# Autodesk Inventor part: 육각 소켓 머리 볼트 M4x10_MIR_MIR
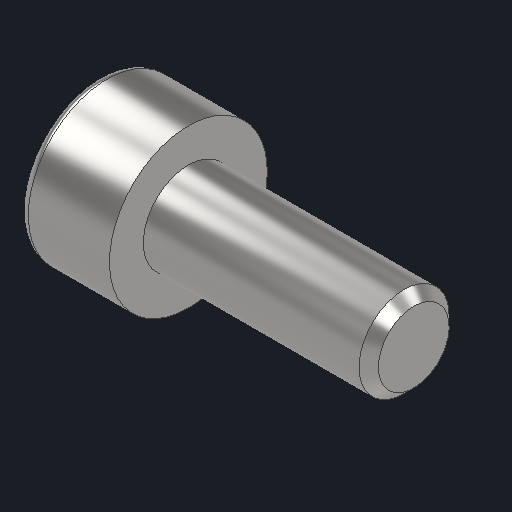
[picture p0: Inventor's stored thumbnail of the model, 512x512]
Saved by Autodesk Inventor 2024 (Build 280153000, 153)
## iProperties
Created: 2024-05
Part Number: 육각 소켓 머리 볼트 M4x10_MIR_MIR
Material: 강철, 연강
Description: 6각머리 태핑 나사
Document SubType Name: Modeling
Designer: kh_501
Density: 7.85 g/cm^3
Appearance: 기본값
Author: jhkim
Sending System: Autodesk Inventor 2025
Preprocessor: ST-DEVELOPER v20
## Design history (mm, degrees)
derived "육각 소켓 머리 볼트 M4x10_MIR.ipt"
feature "솔리드1::육각 소켓 머리 볼트 M4x10_MIR.ipt" dims "d0" = 10
tag "피쳐 태그1"
node "솔리드1"
